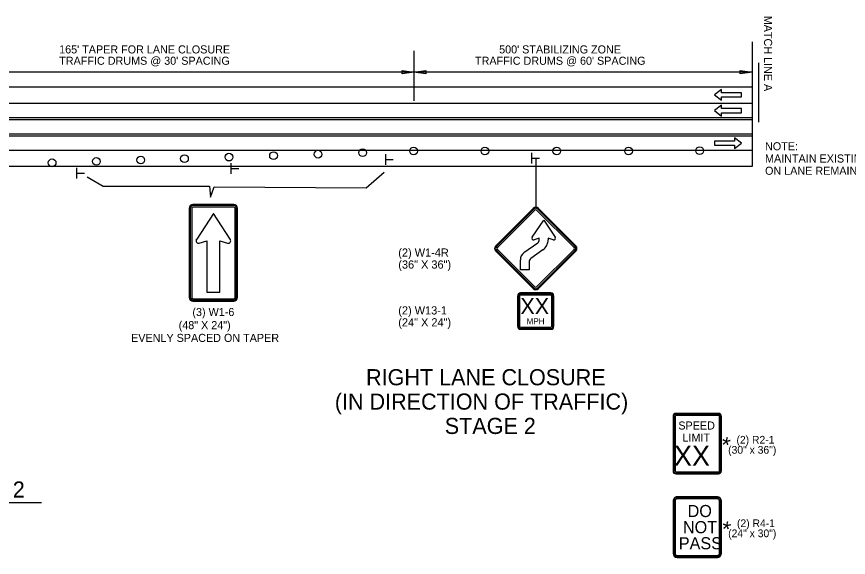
# Model space of a CAD drawing. Extents: x 1930579 to 1938445, y 596452 to 597630.
# Drawn here: x 1936946 to 1937565, y 597140 to 597543 of the extents above; entities that cross this region are included whole.
import ezdxf

# ---------------------------------------------------------------- set-up
doc = ezdxf.new("R2010")
doc.units = 0
for name, color, linetype in [('Default', 7, 'Continuous'), ('P_TC_Signs_Permanent', 7, 'Continuous'), ('R_Border', 7, 'Continuous'), ('R_Striping', 7, 'Continuous')]:
    doc.layers.add(name, color=color, linetype=linetype)

msp = doc.modelspace()

# ---------------------------------------------------------------- linework, layer by layer
at = {"layer": 'Default'}
for p, q in [((1937493.2, 597523.93), (1937493.2, 597431.19)), ((1937241.46, 597517.31), (1937241.46, 597480.01)), ((1937497.86, 597508.25), (1937497.86, 597464.19)), ((1937241.46, 597501.43), (1936874.25, 597501.43)), ((1937232.6, 597500.1), (1937232.6, 597502.76)), ((1937232.6, 597502.76), (1937241.46, 597501.43)), ((1937241.46, 597501.43), (1937232.6, 597500.1)), ((1937241.46, 597501.43), (1937250.33, 597502.76)), ((1937493.2, 597501.43), (1937241.46, 597501.43)), ((1937250.33, 597500.1), (1937241.46, 597501.43)), ((1937250.33, 597502.76), (1937250.33, 597500.1)), ((1937484.34, 597500.1), (1937484.34, 597502.76)), ((1937484.34, 597502.76), (1937493.2, 597501.43)), ((1937493.2, 597501.43), (1937484.34, 597500.1)), ((1937493.2, 597490.19), (1936493.11, 597490.19)), ((1937493.2, 597478.19), (1936493.3, 597478.19)), ((1937493.2, 597466.02), (1936492.72, 597466.02)), ((1937493.2, 597467.4), (1936493.46, 597467.4)), ((1937493.2, 597455.23), (1936493.31, 597455.23)), ((1937493.2, 597453.85), (1936493.31, 597453.85)), ((1937493.2, 597443.19), (1936493.31, 597443.19)), ((1937329.26, 597433.42), (1937329.26, 597441.4)), ((1937220.47, 597432.53), (1937220.47, 597440.51)), ((1937220.59, 597436.5), (1937226.04, 597436.5)), ((1937329.38, 597437.39), (1937334.82, 597437.39)), ((1937493.2, 597431.19), (1936493.31, 597431.19)), ((1936990.55, 597422.26), (1936990.55, 597430.24)), ((1937105.51, 597425.75), (1937105.51, 597433.73)), ((1937105.63, 597429.72), (1937111.08, 597429.72)), ((1936990.67, 597426.23), (1936996.12, 597426.23)), ((1936835.84, 597181.22), (1936964.15, 597181.22))]:
    msp.add_line(p, q, dxfattribs=at)
for centre in [(1937136.93, 597439.28), (1937170.08, 597440.38), (1937203.23, 597441.48), (1937241.17, 597442.71), (1937294.26, 597442.71), (1937347.73, 597442.71), (1937401.2, 597442.71), (1937454.1, 597442.98), (1936972.12, 597433.95), (1937005.1, 597435), (1937038.09, 597436.04), (1937070.62, 597437.08), (1937103.77, 597438.18)]:
    msp.add_circle(centre, 2.87, dxfattribs=at)
at = {"layer": 'P_TC_Signs_Permanent'}
for p, q in [((1937074.16, 597400.12), (1937074.16, 597333.75)), ((1937074.91, 597400.12), (1937074.91, 597333.75)), ((1937076.03, 597400.12), (1937076.03, 597333.75)), ((1937107.35, 597402.94), (1937076.97, 597402.94)), ((1937107.35, 597402.19), (1937076.97, 597402.19)), ((1937107.35, 597401.06), (1937076.97, 597401.06)), ((1937108.28, 597333.75), (1937108.28, 597400.12)), ((1937109.41, 597333.75), (1937109.41, 597400.12)), ((1937110.16, 597333.75), (1937110.16, 597400.12)), ((1937302.27, 597372.17), (1937330.11, 597400.02)), ((1937302.8, 597371.64), (1937330.64, 597399.49)), ((1937331.44, 597398.69), (1937303.6, 597370.85)), ((1937360.61, 597370.85), (1937332.76, 597398.69)), ((1937333.56, 597399.49), (1937361.4, 597371.64)), ((1937334.09, 597400.02), (1937361.93, 597372.17)), ((1937323.34, 597367.11), (1937333.56, 597374.47)), ((1937330.11, 597340.35), (1937302.27, 597368.2)), ((1937330.64, 597340.88), (1937302.8, 597368.73)), ((1937303.6, 597369.52), (1937331.44, 597341.68)), ((1937337.39, 597369.14), (1937328.35, 597362.62)), ((1937332.76, 597341.68), (1937360.61, 597369.52)), ((1937361.4, 597368.73), (1937333.56, 597340.88)), ((1937361.93, 597368.2), (1937334.09, 597340.35)), ((1937343.35, 597337.06), (1937320.85, 597337.06)), ((1937343.35, 597336.49), (1937320.85, 597336.49)), ((1937076.97, 597332.81), (1937107.35, 597332.81)), ((1937076.97, 597331.69), (1937107.35, 597331.69)), ((1937076.97, 597330.94), (1937107.35, 597330.94)), ((1937318.6, 597334.81), (1937318.6, 597312.31)), ((1937319.16, 597334.81), (1937319.16, 597312.31)), ((1937320.1, 597334.81), (1937320.1, 597312.31)), ((1937343.35, 597335.56), (1937320.85, 597335.56)), ((1937344.1, 597312.31), (1937344.1, 597334.81)), ((1937345.04, 597312.31), (1937345.04, 597334.81)), ((1937345.6, 597312.31), (1937345.6, 597334.81)), ((1937320.85, 597311.56), (1937343.35, 597311.56)), ((1937320.85, 597310.62), (1937343.35, 597310.62)), ((1937320.85, 597310.06), (1937343.35, 597310.06)), ((1937434.28, 597245.17), (1937434.28, 597204.67)), ((1937434.84, 597245.17), (1937434.85, 597204.67)), ((1937435.78, 597245.17), (1937435.78, 597204.67)), ((1937468.03, 597247.43), (1937436.53, 597247.42)), ((1937468.03, 597246.86), (1937436.53, 597246.86)), ((1937468.03, 597245.93), (1937436.53, 597245.92)), ((1937468.78, 597204.68), (1937468.78, 597245.18)), ((1937469.72, 597204.68), (1937469.72, 597245.18)), ((1937470.28, 597204.68), (1937470.28, 597245.18)), ((1937436.53, 597203.92), (1937468.03, 597203.93)), ((1937436.53, 597202.99), (1937468.03, 597202.99)), ((1937436.53, 597202.42), (1937468.03, 597202.43)), ((1937434.3, 597182.29), (1937434.3, 597143.29)), ((1937434.9, 597182.29), (1937434.9, 597143.29)), ((1937435.8, 597182.29), (1937435.8, 597143.29)), ((1937467.3, 597185.29), (1937437.3, 597185.29)), ((1937467.3, 597184.69), (1937437.3, 597184.69)), ((1937467.3, 597183.79), (1937437.3, 597183.79)), ((1937468.8, 597143.29), (1937468.8, 597182.29)), ((1937469.7, 597143.29), (1937469.7, 597182.29)), ((1937470.3, 597143.29), (1937470.3, 597182.29)), ((1937437.3, 597141.79), (1937467.3, 597141.79)), ((1937437.3, 597140.89), (1937467.3, 597140.89)), ((1937437.3, 597140.29), (1937467.3, 597140.29))]:
    msp.add_line(p, q, dxfattribs=at)
for points in [[(1937104.6, 597377.19), (1937092.16, 597396.19), (1937079.75, 597377.18)], [(1937329.42, 597378.71), (1937338.01, 597391.28), (1937346.59, 597378.71)], [(1937081.52, 597374.23), (1937087.28, 597375.95), (1937087.28, 597337.69), (1937097.03, 597337.69), (1937097.03, 597375.95), (1937102.78, 597374.2)], [(1937334.73, 597376.75), (1937334.73, 597377.94), (1937330.91, 597376.72)], [(1937345.11, 597376.72), (1937341.29, 597377.94), (1937341.29, 597376.75)], [(1937327.18, 597360.34), (1937327.18, 597354.25), (1937320.62, 597354.25), (1937320.62, 597361.78)]]:
    msp.add_lwpolyline(points, dxfattribs=at)
for centre, radius, start, end in [((1937076.97, 597400.12), 2.81, 90, 180), ((1937076.97, 597400.12), 2.06, 90, 180), ((1937076.97, 597400.12), 0.938, 90, 180), ((1937107.35, 597400.12), 2.81, 360, 90), ((1937107.35, 597400.12), 2.06, 360, 90), ((1937107.35, 597400.12), 0.938, 360, 90), ((1937332.1, 597398.03), 2.81, 45, 135), ((1937332.1, 597398.03), 2.06, 45, 135), ((1937332.1, 597398.03), 0.937, 45, 135), ((1937081.04, 597375.93), 1.76, 146.59943, 285.96908), ((1937016.95, 597418.19), 75, 326.59943, 326.85697), ((1937103.28, 597375.93), 1.8, 254.03093, 33.47548), ((1937167.34, 597418.29), 75, 213.2286, 213.47548), ((1937330.51, 597377.97), 1.31, 145.6763, 287.81282), ((1937331.91, 597376.75), 2.81, 305.77329, 0), ((1937331.91, 597376.75), 9.38, 305.77329, 0), ((1937345.51, 597377.97), 1.31, 252.18718, 34.3237), ((1937304.26, 597370.18), 2.81, 135, 225), ((1937304.26, 597370.18), 2.06, 135, 225), ((1937304.26, 597370.18), 0.938, 135, 225), ((1937327.18, 597361.78), 6.56, 125.77329, 180), ((1937359.94, 597370.18), 0.937, 315, 45), ((1937359.94, 597370.18), 2.06, 315, 45), ((1937359.94, 597370.18), 2.81, 315, 45), ((1937329.99, 597360.34), 2.81, 125.77329, 180), ((1937320.85, 597334.81), 2.25, 90, 180), ((1937320.85, 597334.81), 1.69, 90, 180), ((1937332.1, 597342.34), 2.81, 225, 315), ((1937332.1, 597342.34), 2.06, 225, 315), ((1937332.1, 597342.34), 0.937, 225, 315), ((1937343.35, 597334.81), 2.25, 360, 90), ((1937343.35, 597334.81), 1.69, 360, 90), ((1937076.97, 597333.75), 2.81, 180, 270), ((1937076.97, 597333.75), 2.06, 180, 270), ((1937076.97, 597333.75), 0.937, 180, 270), ((1937107.35, 597333.75), 2.81, 270, 360), ((1937107.35, 597333.75), 2.06, 270, 360), ((1937107.35, 597333.75), 0.938, 270, 360), ((1937320.85, 597334.81), 0.75, 90, 180), ((1937343.35, 597334.81), 0.75, 360, 90), ((1937320.85, 597312.31), 2.25, 180, 270), ((1937320.85, 597312.31), 1.69, 180, 270), ((1937320.85, 597312.31), 0.75, 180, 270), ((1937343.35, 597312.31), 2.25, 270, 360), ((1937343.35, 597312.31), 1.69, 270, 360), ((1937343.35, 597312.31), 0.75, 270, 360), ((1937436.53, 597245.17), 2.25, 90.00298, 180.00298), ((1937436.53, 597245.17), 1.69, 90.00298, 180.00298), ((1937436.53, 597245.17), 0.75, 90.00298, 180.00298), ((1937468.03, 597245.18), 2.25, 0.00298, 90.00298), ((1937468.03, 597245.18), 1.69, 0.00298, 90.00298), ((1937468.03, 597245.18), 0.75, 0.00298, 90.00298), ((1937436.53, 597204.67), 2.25, 180.00298, 270.00298), ((1937436.53, 597204.67), 1.69, 180.00298, 270.00298), ((1937436.53, 597204.67), 0.75, 180.00298, 270.00298), ((1937468.03, 597204.68), 2.25, 270.00298, 0.00298), ((1937468.03, 597204.68), 1.69, 270.00298, 0.00298), ((1937468.03, 597204.68), 0.75, 270.00298, 0.00298), ((1937437.3, 597182.29), 3, 90.00298, 180.00298), ((1937437.3, 597182.29), 2.4, 90.00298, 180.00298), ((1937437.3, 597182.29), 1.5, 90.00298, 180.00298), ((1937467.3, 597182.29), 3, 0.00298, 90.00298), ((1937467.3, 597182.29), 2.4, 0.00298, 90.00298), ((1937467.3, 597182.29), 1.5, 0.00298, 90.00298), ((1937437.3, 597143.29), 3, 180.00298, 270.00298), ((1937437.3, 597143.29), 2.4, 180.00298, 270.00298), ((1937437.3, 597143.29), 1.5, 180.00298, 270.00298), ((1937467.3, 597143.29), 3, 270.00298, 0.00298), ((1937467.3, 597143.29), 2.4, 270.00298, 0.00298), ((1937467.3, 597143.29), 1.5, 270.00298, 0.00298)]:
    msp.add_arc(centre, radius, start, end, dxfattribs=at)
at = {"layer": 'R_Border'}
msp.add_line((1937332.1, 597437.39), (1937332.1, 597400.84), dxfattribs=at)
msp.add_lwpolyline([(1936998.23, 597423.61), (1937010.04, 597416.66), (1937089.24, 597416.66), (1937089.94, 597408.32), (1937092.72, 597415.97), (1937205.97, 597415.27), (1937219.17, 597427.09)], dxfattribs=at)
at = {"layer": 'R_Striping'}
for points in [[(1937470.43, 597488.56), (1937465.23, 597484.56), (1937470.43, 597480.56), (1937470.43, 597483.06), (1937485.14, 597483.06), (1937485.14, 597486.06), (1937470.43, 597486.06)], [(1937470.43, 597476.78), (1937465.23, 597472.78), (1937470.43, 597468.78), (1937470.43, 597471.28), (1937485.14, 597471.28), (1937485.14, 597474.28), (1937470.43, 597474.28)], [(1937479.95, 597444.61), (1937485.14, 597448.61), (1937479.95, 597452.61), (1937479.95, 597450.11), (1937465.23, 597450.11), (1937465.23, 597447.11), (1937479.95, 597447.11)]]:
    msp.add_lwpolyline(points, close=True, dxfattribs=at)

# ---------------------------------------------------------------- texts
at = {"layer": 'Default'}
for s, height, rotation, p in [('MATCH LINE A', 5.9996, 270, (1937502.02, 597543.42)), ("165' TAPER FOR LANE CLOSURE", 6, 360, (1936977.35, 597515.36)), ("500' STABILIZING ZONE", 6, 360, (1937304.83, 597515.36)), ("TRAFFIC DRUMS @ 30' SPACING", 6, 360, (1936977.42, 597506.93)), ("TRAFFIC DRUMS @ 60' SPACING", 6, 360, (1937286.9, 597506.93)), ('RIGHT LANE CLOSURE', 12, 360, (1937205.79, 597268.37)), ('(IN DIRECTION OF TRAFFIC)', 12, 360, (1937182.54, 597250.25)), ('STAGE 2', 12, 360, (1937264.37, 597232.13)), ('STAGES 1   & 2', 12, 360, (1936835.84, 597184.79))]:
    msp.add_text(s, height=height, rotation=rotation, dxfattribs=at).set_placement(p)
at = {"layer": 'P_TC_Signs_Permanent'}
for s, height, rotation, p in [('XX', 12, 360, (1937320.64, 597321.31)), ('MPH', 4.5, 360, (1937325.27, 597313.81)), ('SPEED', 6, 0.00298, (1937438.21, 597235.42)), ('LIMIT', 6, 0.00298, (1937441.3, 597226.42)), ('XX', 15, 0.00298, (1937434.98, 597208.42)), ('DO', 9, 0.00298, (1937445.13, 597170.29)), ('NOT', 9, 359.96262, (1937441.65, 597158.3)), ('PASS', 9, 0.00298, (1937438.59, 597146.29))]:
    msp.add_text(s, height=height, rotation=rotation, dxfattribs=at).set_placement(p)
at = {"layer": 'R_Border'}
for s, height, rotation, p in [('NOTE:', 6, 360, (1937502.75, 597443.27)), ('MAINTAIN EXISTING LANE WIDTH', 6, 360, (1937502.75, 597434.16)), ('ON LANE REMAINING OPEN', 6, 360, (1937502.75, 597425.05)), ('(2) W1-4R', 6.099, 360, (1937229.77, 597364.09)), ('(36" X 36")', 6.0988, 360, (1937229.77, 597355.21)), ('(3) W1-6', 6, 0.00754, (1937076.54, 597319.93)), ('(2) W13-1', 6.099, 360, (1937229.77, 597321.07)), ('(24" X 24")', 6.0988, 360, (1937229.77, 597312.19)), ('(48" X 24")', 6, 0.00754, (1937066.32, 597310.13)), ('EVENLY SPACED ON TAPER', 6, 0.00754, (1937030.91, 597300.64)), ('(2) R2-1', 5.76, 0.00298, (1937481.49, 597224.93)), ('*', 12, 135.00298, (1937482.37, 597230.71)), ('(30" x 36")', 5.76, 0.00298, (1937475.28, 597217.44)), ('(2) R4-1', 5.76, 0.00298, (1937481.88, 597162.79)), ('*', 12, 135.00298, (1937482.67, 597167.99)), ('(24" x 30")', 5.76, 0.00298, (1937475.3, 597155.3))]:
    msp.add_text(s, height=height, rotation=rotation, dxfattribs=at).set_placement(p)

doc.saveas('drawing.dxf')
